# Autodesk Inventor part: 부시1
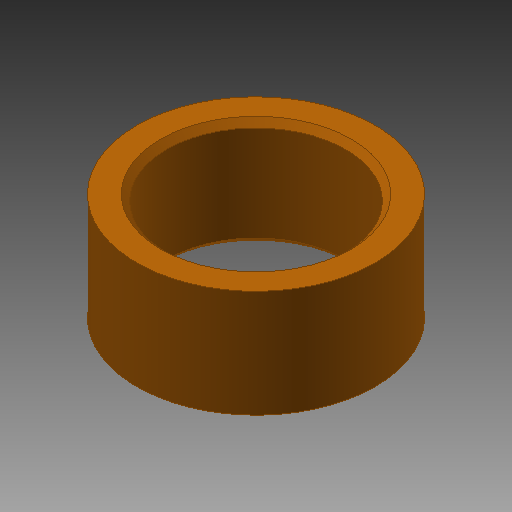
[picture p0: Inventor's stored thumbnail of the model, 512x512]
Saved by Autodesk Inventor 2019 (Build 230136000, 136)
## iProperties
Created: 2016-08
Part Number: 부시1
Material: 강철, 탄소
Document SubType Name: Modeling
Designer: mduedu
Density: 7.87 g/cm^3
Appearance: 주황색
Author: mduedu
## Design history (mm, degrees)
sketch "스케치1"
  geometry: C1 r 7.5 at (0, 0); C2 r 10 at (0, 0); 1 further point
  constraints: 2 centre point, 2 coincident
  dimensions: "d0" = 15 diameter of C1; "d1" = 20 diameter of C2
extrude "돌출1" new body sketch "스케치1" stored distance "d2" = 9; taper "d3" = 0 deg
chamfer "모따기1" distance "d4" = 0.5; stored, may be unused: second distance "d5" = 2, angle "d6" = 45 deg
node "솔리드1"
